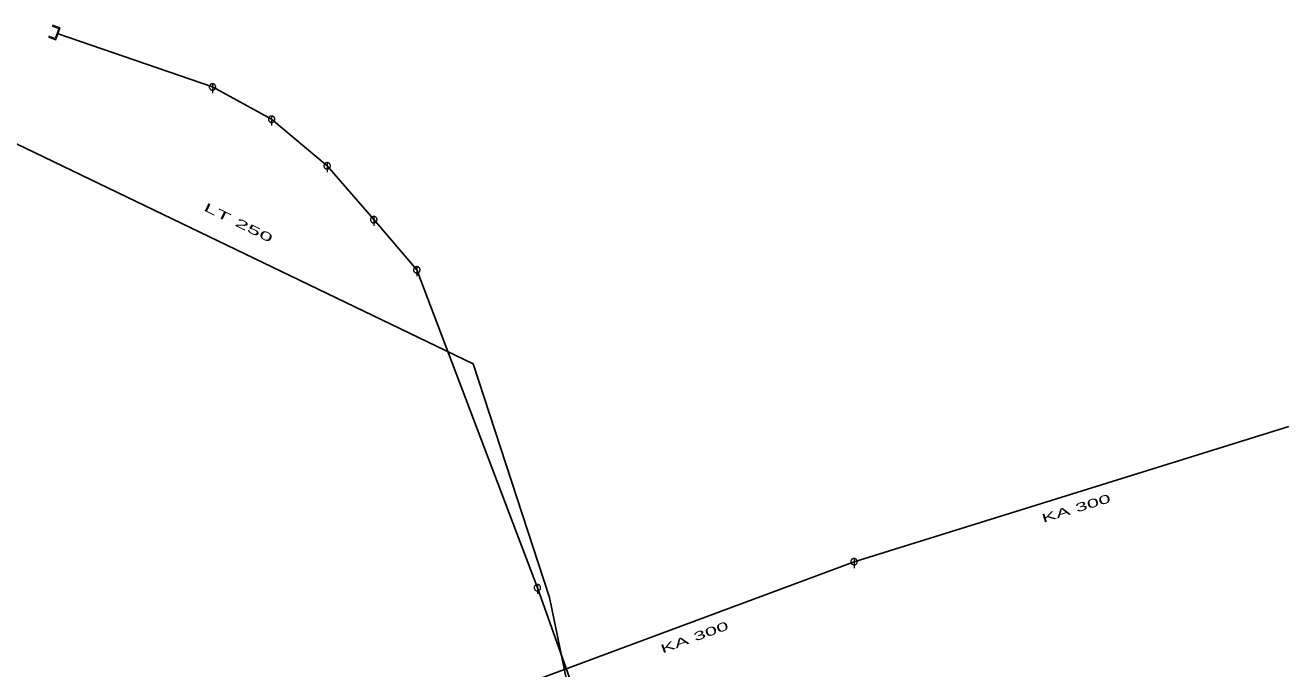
# Model space of a CAD drawing. Extents: x -687468 to -685917, y -974192 to -973456.
# Drawn here: x -686064.9 to -685966.5, y -973820.8 to -973770.7 of the extents above; entities that cross this region are included whole.
import ezdxf
from ezdxf.enums import TextEntityAlignment as Align

# ---------------------------------------------------------------- set-up
doc = ezdxf.new("R2010")
doc.units = 0
doc.header["$LTSCALE"] = 0.27
for name, color, linetype, lineweight in [('1', 7, 'Continuous', 13), ('14', 7, 'Continuous', 25), ('17', 7, 'Continuous', 25), ('22', 7, 'Continuous', 13), ('29', 7, 'Continuous', 13)]:
    doc.layers.add(name, color=color, linetype=linetype, lineweight=lineweight)

msp = doc.modelspace()

# ---------------------------------------------------------------- linework, layer by layer
at = {"layer": '14'}
for p, q in [((-685966.541, -973801.967), (-686000.392, -973812.491)), ((-686000.392, -973812.491), (-686026.164, -973822.081)), ((-686016.971, -973837.108), (-686025.047, -973814.512))]:
    msp.add_line(p, q, dxfattribs=at)
msp.add_lwpolyline([(-686025.047, -973814.512), (-686034.438, -973789.774), (-686037.787, -973785.867), (-686041.416, -973781.68), (-686045.742, -973778.052), (-686050.347, -973775.54), (-686062.369, -973771.41)], dxfattribs=at)
at = {"layer": '17'}
msp.add_lwpolyline([(-686097.397, -973770.949), (-686068.427, -973778.603), (-686030.059, -973797.083), (-686024.092, -973815.278), (-686022.102, -973824.943), (-686038.017, -973844.276)], dxfattribs=at)
at = {"layer": '22'}
for p, q in [((-686050.346, -973775.288), (-686050.347, -973776.032)), ((-686045.741, -973777.8), (-686045.742, -973778.544)), ((-686041.415, -973781.428), (-686041.416, -973782.172)), ((-686037.786, -973785.615), (-686037.787, -973786.358)), ((-686034.437, -973789.522), (-686034.438, -973790.266)), ((-686000.391, -973812.239), (-686000.392, -973812.983)), ((-686025.046, -973814.26), (-686025.047, -973815.004))]:
    msp.add_line(p, q, dxfattribs=at)
for points in [[(-686050.095, -973775.54), (-686050.096, -973775.514), (-686050.1, -973775.488), (-686050.106, -973775.462), (-686050.116, -973775.438), (-686050.128, -973775.414), (-686050.142, -973775.392), (-686050.159, -973775.371), (-686050.177, -973775.353), (-686050.198, -973775.336), (-686050.22, -973775.322), (-686050.244, -973775.31), (-686050.268, -973775.3), (-686050.294, -973775.294), (-686050.32, -973775.29), (-686050.346, -973775.288), (-686050.372, -973775.289), (-686050.398, -973775.293), (-686050.424, -973775.299), (-686050.449, -973775.309), (-686050.472, -973775.321), (-686050.494, -973775.335), (-686050.515, -973775.352), (-686050.533, -973775.37), (-686050.55, -973775.391), (-686050.564, -973775.413), (-686050.576, -973775.437), (-686050.586, -973775.461), (-686050.593, -973775.487), (-686050.597, -973775.513), (-686050.598, -973775.539), (-686050.598, -973775.565), (-686050.594, -973775.591), (-686050.587, -973775.617), (-686050.577, -973775.642), (-686050.565, -973775.665), (-686050.551, -973775.687), (-686050.534, -973775.708), (-686050.516, -973775.726), (-686050.495, -973775.743), (-686050.473, -973775.757), (-686050.45, -973775.769), (-686050.425, -973775.779), (-686050.399, -973775.786), (-686050.373, -973775.79), (-686050.347, -973775.792), (-686050.321, -973775.791), (-686050.295, -973775.787), (-686050.269, -973775.78), (-686050.245, -973775.77), (-686050.221, -973775.758), (-686050.199, -973775.744), (-686050.178, -973775.727), (-686050.16, -973775.709), (-686050.143, -973775.688), (-686050.129, -973775.666), (-686050.117, -973775.643), (-686050.107, -973775.618), (-686050.101, -973775.592), (-686050.097, -973775.566)], [(-686045.49, -973778.052), (-686045.491, -973778.026), (-686045.495, -973778), (-686045.501, -973777.974), (-686045.511, -973777.95), (-686045.523, -973777.926), (-686045.537, -973777.904), (-686045.554, -973777.883), (-686045.572, -973777.865), (-686045.593, -973777.848), (-686045.615, -973777.834), (-686045.639, -973777.822), (-686045.663, -973777.812), (-686045.689, -973777.806), (-686045.715, -973777.802), (-686045.741, -973777.8), (-686045.767, -973777.801), (-686045.793, -973777.805), (-686045.819, -973777.811), (-686045.844, -973777.821), (-686045.867, -973777.833), (-686045.889, -973777.847), (-686045.91, -973777.864), (-686045.928, -973777.882), (-686045.945, -973777.903), (-686045.959, -973777.925), (-686045.971, -973777.949), (-686045.981, -973777.973), (-686045.988, -973777.999), (-686045.992, -973778.025), (-686045.994, -973778.051), (-686045.993, -973778.077), (-686045.989, -973778.103), (-686045.982, -973778.129), (-686045.972, -973778.154), (-686045.96, -973778.177), (-686045.946, -973778.199), (-686045.929, -973778.22), (-686045.911, -973778.238), (-686045.89, -973778.255), (-686045.868, -973778.269), (-686045.845, -973778.281), (-686045.82, -973778.291), (-686045.794, -973778.298), (-686045.768, -973778.302), (-686045.742, -973778.304), (-686045.716, -973778.303), (-686045.69, -973778.299), (-686045.664, -973778.292), (-686045.64, -973778.282), (-686045.616, -973778.27), (-686045.594, -973778.256), (-686045.573, -973778.239), (-686045.555, -973778.221), (-686045.538, -973778.2), (-686045.524, -973778.178), (-686045.512, -973778.155), (-686045.502, -973778.13), (-686045.496, -973778.104), (-686045.492, -973778.078)], [(-686041.164, -973781.68), (-686041.165, -973781.654), (-686041.169, -973781.628), (-686041.175, -973781.602), (-686041.185, -973781.578), (-686041.197, -973781.554), (-686041.211, -973781.532), (-686041.228, -973781.511), (-686041.246, -973781.493), (-686041.267, -973781.476), (-686041.289, -973781.462), (-686041.313, -973781.45), (-686041.337, -973781.44), (-686041.363, -973781.434), (-686041.389, -973781.43), (-686041.415, -973781.428), (-686041.441, -973781.429), (-686041.467, -973781.433), (-686041.493, -973781.439), (-686041.518, -973781.449), (-686041.541, -973781.461), (-686041.563, -973781.475), (-686041.584, -973781.492), (-686041.602, -973781.51), (-686041.619, -973781.531), (-686041.633, -973781.553), (-686041.645, -973781.577), (-686041.655, -973781.601), (-686041.662, -973781.627), (-686041.666, -973781.653), (-686041.668, -973781.679), (-686041.667, -973781.705), (-686041.663, -973781.731), (-686041.656, -973781.757), (-686041.646, -973781.782), (-686041.634, -973781.805), (-686041.62, -973781.827), (-686041.603, -973781.848), (-686041.585, -973781.866), (-686041.564, -973781.883), (-686041.542, -973781.897), (-686041.519, -973781.909), (-686041.494, -973781.919), (-686041.468, -973781.926), (-686041.442, -973781.93), (-686041.416, -973781.932), (-686041.39, -973781.931), (-686041.364, -973781.927), (-686041.338, -973781.92), (-686041.314, -973781.91), (-686041.29, -973781.898), (-686041.268, -973781.884), (-686041.247, -973781.867), (-686041.229, -973781.849), (-686041.212, -973781.828), (-686041.198, -973781.806), (-686041.186, -973781.783), (-686041.176, -973781.758), (-686041.17, -973781.732), (-686041.166, -973781.706)], [(-686037.535, -973785.867), (-686037.536, -973785.841), (-686037.54, -973785.815), (-686037.546, -973785.789), (-686037.556, -973785.765), (-686037.568, -973785.741), (-686037.582, -973785.719), (-686037.599, -973785.698), (-686037.617, -973785.68), (-686037.638, -973785.663), (-686037.66, -973785.649), (-686037.684, -973785.637), (-686037.708, -973785.627), (-686037.734, -973785.621), (-686037.76, -973785.617), (-686037.786, -973785.615), (-686037.812, -973785.616), (-686037.838, -973785.62), (-686037.864, -973785.626), (-686037.889, -973785.636), (-686037.912, -973785.648), (-686037.934, -973785.662), (-686037.955, -973785.679), (-686037.973, -973785.697), (-686037.99, -973785.718), (-686038.004, -973785.74), (-686038.016, -973785.764), (-686038.026, -973785.788), (-686038.033, -973785.814), (-686038.037, -973785.84), (-686038.039, -973785.866), (-686038.038, -973785.892), (-686038.034, -973785.918), (-686038.027, -973785.944), (-686038.017, -973785.969), (-686038.005, -973785.992), (-686037.991, -973786.014), (-686037.974, -973786.035), (-686037.956, -973786.053), (-686037.935, -973786.07), (-686037.913, -973786.084), (-686037.89, -973786.096), (-686037.865, -973786.106), (-686037.839, -973786.113), (-686037.813, -973786.117), (-686037.787, -973786.119), (-686037.761, -973786.118), (-686037.735, -973786.114), (-686037.709, -973786.107), (-686037.685, -973786.097), (-686037.661, -973786.085), (-686037.639, -973786.071), (-686037.618, -973786.054), (-686037.6, -973786.036), (-686037.583, -973786.015), (-686037.569, -973785.993), (-686037.557, -973785.97), (-686037.547, -973785.945), (-686037.541, -973785.919), (-686037.537, -973785.893)], [(-686034.186, -973789.774), (-686034.187, -973789.748), (-686034.191, -973789.722), (-686034.197, -973789.696), (-686034.207, -973789.672), (-686034.219, -973789.648), (-686034.233, -973789.626), (-686034.25, -973789.605), (-686034.268, -973789.587), (-686034.289, -973789.57), (-686034.311, -973789.556), (-686034.335, -973789.544), (-686034.359, -973789.534), (-686034.385, -973789.528), (-686034.411, -973789.524), (-686034.437, -973789.522), (-686034.463, -973789.523), (-686034.489, -973789.527), (-686034.515, -973789.533), (-686034.54, -973789.543), (-686034.563, -973789.555), (-686034.585, -973789.569), (-686034.606, -973789.586), (-686034.624, -973789.604), (-686034.641, -973789.625), (-686034.655, -973789.647), (-686034.667, -973789.671), (-686034.677, -973789.695), (-686034.684, -973789.721), (-686034.688, -973789.747), (-686034.69, -973789.773), (-686034.689, -973789.799), (-686034.685, -973789.825), (-686034.678, -973789.851), (-686034.668, -973789.876), (-686034.656, -973789.899), (-686034.642, -973789.921), (-686034.625, -973789.942), (-686034.607, -973789.96), (-686034.586, -973789.977), (-686034.564, -973789.991), (-686034.541, -973790.003), (-686034.516, -973790.013), (-686034.49, -973790.02), (-686034.464, -973790.024), (-686034.438, -973790.026), (-686034.412, -973790.025), (-686034.386, -973790.021), (-686034.36, -973790.014), (-686034.336, -973790.004), (-686034.312, -973789.992), (-686034.29, -973789.978), (-686034.269, -973789.961), (-686034.251, -973789.943), (-686034.234, -973789.922), (-686034.22, -973789.9), (-686034.208, -973789.877), (-686034.198, -973789.852), (-686034.192, -973789.826), (-686034.188, -973789.8)], [(-686000.14, -973812.491), (-686000.141, -973812.465), (-686000.145, -973812.439), (-686000.151, -973812.413), (-686000.161, -973812.389), (-686000.173, -973812.365), (-686000.187, -973812.343), (-686000.204, -973812.322), (-686000.222, -973812.304), (-686000.243, -973812.287), (-686000.265, -973812.273), (-686000.289, -973812.261), (-686000.313, -973812.251), (-686000.339, -973812.245), (-686000.365, -973812.241), (-686000.391, -973812.239), (-686000.417, -973812.24), (-686000.443, -973812.244), (-686000.469, -973812.25), (-686000.494, -973812.26), (-686000.517, -973812.272), (-686000.539, -973812.286), (-686000.56, -973812.303), (-686000.578, -973812.321), (-686000.595, -973812.342), (-686000.609, -973812.364), (-686000.621, -973812.388), (-686000.631, -973812.412), (-686000.638, -973812.438), (-686000.642, -973812.464), (-686000.644, -973812.49), (-686000.643, -973812.516), (-686000.639, -973812.542), (-686000.632, -973812.568), (-686000.622, -973812.593), (-686000.61, -973812.616), (-686000.596, -973812.638), (-686000.579, -973812.659), (-686000.561, -973812.677), (-686000.54, -973812.694), (-686000.518, -973812.708), (-686000.495, -973812.72), (-686000.47, -973812.73), (-686000.444, -973812.737), (-686000.418, -973812.741), (-686000.392, -973812.743), (-686000.366, -973812.742), (-686000.34, -973812.738), (-686000.314, -973812.731), (-686000.29, -973812.721), (-686000.266, -973812.709), (-686000.244, -973812.695), (-686000.223, -973812.678), (-686000.205, -973812.66), (-686000.188, -973812.639), (-686000.174, -973812.617), (-686000.162, -973812.594), (-686000.152, -973812.569), (-686000.146, -973812.543), (-686000.142, -973812.517)], [(-686024.795, -973814.512), (-686024.796, -973814.486), (-686024.8, -973814.46), (-686024.806, -973814.434), (-686024.816, -973814.41), (-686024.828, -973814.386), (-686024.842, -973814.364), (-686024.859, -973814.343), (-686024.877, -973814.325), (-686024.898, -973814.308), (-686024.92, -973814.294), (-686024.944, -973814.282), (-686024.968, -973814.272), (-686024.994, -973814.266), (-686025.02, -973814.262), (-686025.046, -973814.26), (-686025.072, -973814.261), (-686025.098, -973814.265), (-686025.124, -973814.271), (-686025.149, -973814.281), (-686025.172, -973814.293), (-686025.194, -973814.307), (-686025.215, -973814.324), (-686025.233, -973814.342), (-686025.25, -973814.363), (-686025.264, -973814.385), (-686025.276, -973814.409), (-686025.286, -973814.433), (-686025.293, -973814.459), (-686025.297, -973814.485), (-686025.299, -973814.511), (-686025.298, -973814.537), (-686025.294, -973814.563), (-686025.287, -973814.589), (-686025.277, -973814.614), (-686025.265, -973814.637), (-686025.251, -973814.659), (-686025.234, -973814.68), (-686025.216, -973814.698), (-686025.195, -973814.715), (-686025.173, -973814.729), (-686025.15, -973814.741), (-686025.125, -973814.751), (-686025.099, -973814.758), (-686025.073, -973814.762), (-686025.047, -973814.764), (-686025.021, -973814.763), (-686024.995, -973814.759), (-686024.969, -973814.752), (-686024.945, -973814.742), (-686024.921, -973814.73), (-686024.899, -973814.716), (-686024.878, -973814.699), (-686024.86, -973814.681), (-686024.843, -973814.66), (-686024.829, -973814.638), (-686024.817, -973814.615), (-686024.807, -973814.59), (-686024.801, -973814.564), (-686024.797, -973814.538)]]:
    msp.add_lwpolyline(points, close=True, dxfattribs=at)
at = {"layer": '29'}
for points in [[(-686063.122, -973771.675), (-686062.533, -973771.877), (-686062.211, -973770.939), (-686062.799, -973770.737)], [(-686062.828, -973770.819), (-686062.322, -973770.993), (-686062.587, -973771.767), (-686063.093, -973771.593)]]:
    msp.add_lwpolyline(points, dxfattribs=at)

# ---------------------------------------------------------------- texts
at = {"layer": '1'}
for s, rotation, width, p in [('LT 250', 334, 2.1, (-686048.473, -973786.398)), ('KA 300', 17, 1.9, (-685983, -973808.649)), ('KA 300', 20, 1.9, (-686012.701, -973818.681))]:
    msp.add_text(s, height=0.6667, rotation=rotation, dxfattribs=dict(at, width=width)).set_placement(p, align=Align.CENTER)

doc.saveas('drawing.dxf')
